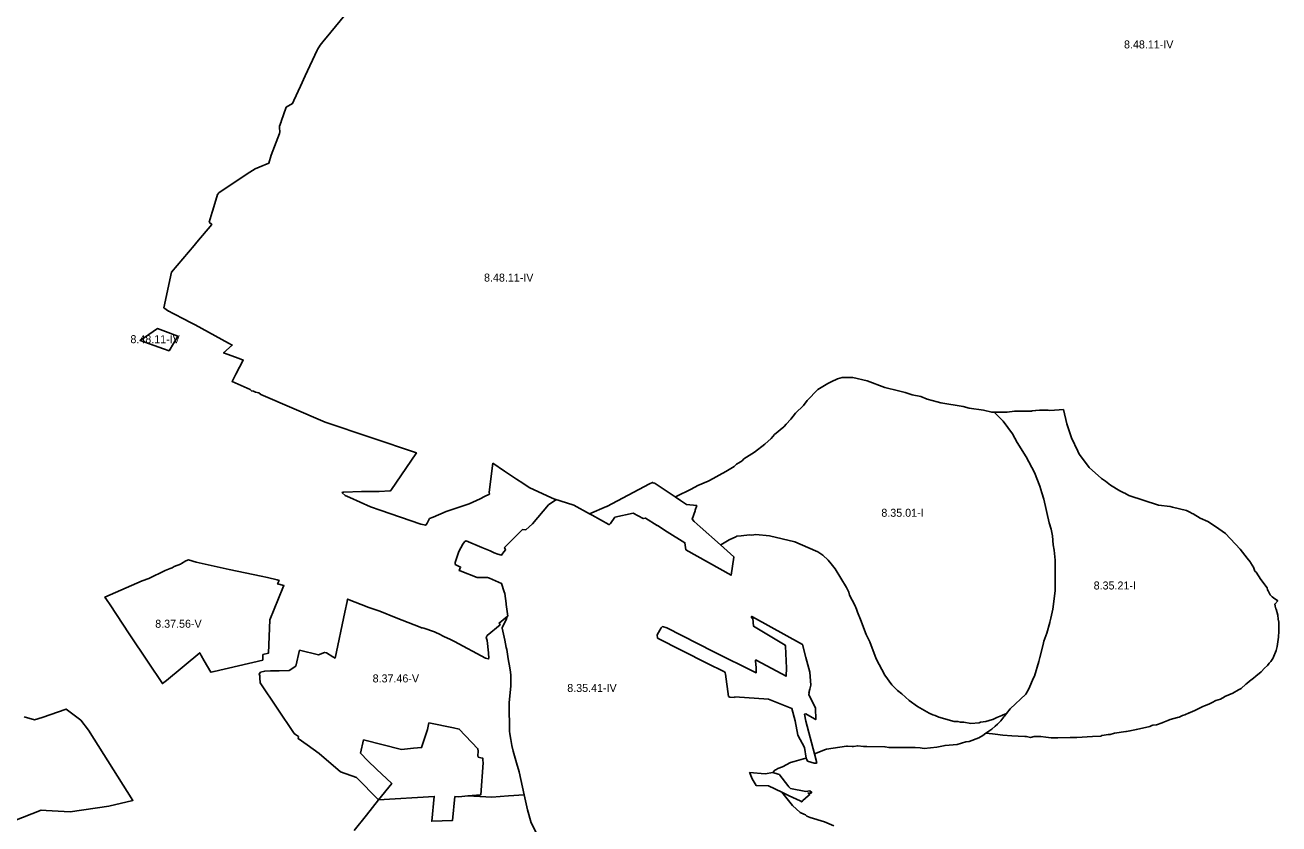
# Model space of a CAD drawing. Extents: x -444937 to -440470, y -1149084 to -1129741.
# Drawn here: x -443286 to -441720, y -1132039 to -1131040 of the extents above; entities that cross this region are included whole.
import ezdxf

# ---------------------------------------------------------------- set-up
doc = ezdxf.new("R2010")
doc.units = 0
doc.layers.add('Vrstva 28', color=7, linetype='Continuous')

msp = doc.modelspace()

# ---------------------------------------------------------------- linework, layer by layer
at = {"layer": 'Vrstva 28'}
for points in [[(-443113.15, -1131393.63), (-443103.68, -1131349.31), (-443075.35, -1131315.72), (-443071.83, -1131311.55), (-443053.26, -1131289.53), (-443056.45, -1131286.51), (-443055.2, -1131282.39), (-443052.68, -1131274.06), (-443052, -1131271.83), (-443046.06, -1131252.22), (-443044.11, -1131249.77), (-443005.5, -1131224.32), (-442999.16, -1131220.19), (-442993.96, -1131218), (-442981.76, -1131212.85), (-442978.94, -1131203.16), (-442968.4, -1131175.73), (-442968.32, -1131173.69), (-442968.47, -1131168.76), (-442968.46, -1131166.69), (-442966.56, -1131161.26), (-442966.43, -1131160.87), (-442960.2, -1131143.04), (-442952.18, -1131138.59), (-442950.71, -1131134.82), (-442942.42, -1131116.8), (-442942.39, -1131116.76), (-442936.4, -1131103.74), (-442921.53, -1131071.78), (-442921.33, -1131071.43), (-442921.05, -1131070.95), (-442917.86, -1131065.53), (-442914.32, -1131061.21), (-442904.54, -1131049.3), (-442887.1, -1131028.05)], [(-442626.15, -1131632.27), (-442628.86, -1131631.02), (-442656.65, -1131618.23), (-442664.68, -1131612.89), (-442672.47, -1131607.71), (-442687.37, -1131597.8), (-442702.14, -1131587.99), (-442706.86, -1131624.1), (-442706.45, -1131626.39), (-442712.53, -1131629.48), (-442718.17, -1131632.34), (-442731.84, -1131638.47), (-442760.3, -1131648.07), (-442776.82, -1131655.27), (-442781.2, -1131657.14), (-442784.1, -1131662.85), (-442786.01, -1131665.41), (-442791.96, -1131664.13), (-442842.68, -1131646.65), (-442854.89, -1131642.45), (-442880.78, -1131630.8), (-442886.56, -1131628.2), (-442886.64, -1131628.13), (-442890.17, -1131625.01), (-442889.75, -1131624.16), (-442888.05, -1131623.95), (-442866.36, -1131623.1), (-442844.26, -1131623.1), (-442830.44, -1131622.46), (-442829.38, -1131621.83), (-442797.54, -1131574.91), (-442911.64, -1131536.4), (-442991.79, -1131501.93), (-442994.55, -1131500.02), (-442998.59, -1131499.17), (-443001.14, -1131497.68), (-443003.69, -1131497.46), (-443005.4, -1131495.76), (-443027.88, -1131485.8), (-443023.15, -1131476.76), (-443013.87, -1131459.02), (-443019.04, -1131457.15), (-443038.38, -1131449.99), (-443027.63, -1131440.22), (-443032.18, -1131437.94), (-443073.85, -1131414.98), (-443083.04, -1131410.25), (-443085.34, -1131409.07), (-443103.18, -1131399.89), (-443105.88, -1131398.5), (-443106.11, -1131398.38), (-443107.1, -1131397.87), (-443113.15, -1131393.63)], [(-443095.75, -1131428.94), (-443106.54, -1131447.3), (-443113.62, -1131444.8), (-443131.18, -1131438.59), (-443142.76, -1131434.49), (-443120.91, -1131419.75), (-443114.47, -1131422.1)], [(-443114.47, -1131422.1), (-443095.75, -1131428.94)], [(-442474.49, -1131630), (-442473.06, -1131629.26), (-442454.42, -1131620.23), (-442446.28, -1131615.86), (-442433.1, -1131610.12), (-442431.6, -1131609.3), (-442411.2, -1131598.21), (-442400.79, -1131591.83), (-442398.02, -1131589.28), (-442397.75, -1131589.11), (-442394.94, -1131587.38), (-442390.8, -1131584.82), (-442388.46, -1131582.48), (-442375.49, -1131574.19), (-442362.52, -1131563.98), (-442354.65, -1131556.97), (-442350.19, -1131551.86), (-442338.71, -1131542.3), (-442338.35, -1131541.92), (-442335.59, -1131538.96), (-442329.78, -1131532.73), (-442324.04, -1131525.5), (-442314.26, -1131515.72), (-442309.37, -1131509.35), (-442296.19, -1131495.95), (-442283.65, -1131488.09), (-442279.64, -1131486.19), (-442271.53, -1131482.35), (-442265.79, -1131480.65), (-442252.4, -1131480.86), (-442234.54, -1131485.11), (-442212.43, -1131493.4), (-442195.64, -1131497.46), (-442186.92, -1131499.57), (-442178.41, -1131502.54), (-442167.36, -1131504.67), (-442159.7, -1131507.86), (-442147.32, -1131511.11), (-442142.7, -1131512.32), (-442114.63, -1131517), (-442106.98, -1131518.91), (-442089.12, -1131521.46)], [(-442089.12, -1131521.46), (-442078.92, -1131524.23), (-442075.85, -1131524.21)], [(-442075.85, -1131524.21), (-442059.78, -1131524.01), (-442050.43, -1131522.74), (-442043.63, -1131522.86), (-442040.93, -1131522.88), (-442029.17, -1131522.95), (-442028.32, -1131522.31), (-442024.21, -1131521.97), (-442023.77, -1131521.93), (-442019.51, -1131521.58), (-442018.12, -1131521.46), (-442014.6, -1131521.46), (-442008.76, -1131521.46), (-442006.21, -1131522.1), (-442000.63, -1131521.68), (-441994.94, -1131521.25), (-441989.36, -1131520.83)], [(-442075.85, -1131524.21), (-442064.89, -1131535.28), (-442052.98, -1131551.01), (-442047.03, -1131562.07), (-442035.97, -1131579.93), (-442025.56, -1131599.49), (-442018.96, -1131616.49), (-442016.35, -1131624.78), (-442013.86, -1131632.65), (-442007.27, -1131662.41), (-442004.93, -1131670.07), (-442003.23, -1131678.57), (-442002.38, -1131689.63), (-442000.89, -1131696.43), (-441999.62, -1131709.19), (-441999.63, -1131710.92), (-441999.66, -1131716), (-441999.74, -1131730.96), (-441999.83, -1131747.45), (-442002.81, -1131770.41), (-442003.58, -1131774.07), (-442005.09, -1131781.26), (-442006.21, -1131786.57), (-442006.24, -1131786.68), (-442010.04, -1131800.18), (-442013.86, -1131810.38), (-442014.79, -1131814.23), (-442018.75, -1131830.79), (-442020.28, -1131835.78), (-442025.77, -1131853.75), (-442026.8, -1131856.18), (-442032.57, -1131869.69), (-442036.4, -1131876.29), (-442055.96, -1131894.57), (-442060.5, -1131900.51)], [(-441989.36, -1131520.83), (-441985.29, -1131538.47), (-441984.95, -1131539.96), (-441979.21, -1131556.33), (-441971.4, -1131572.97), (-441971.27, -1131573.24), (-441969.43, -1131577.16), (-441957.1, -1131593.11), (-441942.01, -1131606.93), (-441936.69, -1131610.33), (-441930.53, -1131615.43), (-441919.05, -1131622.45), (-441913.87, -1131624.69), (-441912.67, -1131625.21), (-441907.57, -1131628.4), (-441870.57, -1131640.3), (-441856.12, -1131642.01), (-441853.35, -1131642.7), (-441835.71, -1131647.11), (-441831.53, -1131649.09), (-441828.53, -1131650.52), (-441827.2, -1131651.15), (-441818.7, -1131656.67), (-441808.92, -1131660.71), (-441799.35, -1131666.88), (-441787.02, -1131675.6), (-441768.53, -1131695.15), (-441759.88, -1131706.4), (-441756.29, -1131711.06), (-441755.77, -1131711.74), (-441751.73, -1131718.54), (-441751.53, -1131719.09), (-441750.24, -1131722.58), (-441748.76, -1131723.85), (-441743.02, -1131733), (-441735.15, -1131743.63), (-441734.51, -1131746.18), (-441733.83, -1131747.37), (-441731.11, -1131752.13), (-441730.35, -1131753.03), (-441728.77, -1131754.89), (-441727.25, -1131755.98), (-441721.67, -1131759.97), (-441725.58, -1131763.82), (-441724.93, -1131766.17), (-441724.91, -1131766.27), (-441723.93, -1131769.8), (-441723.8, -1131770.25), (-441721.76, -1131777.64), (-441721.06, -1131782.54), (-441721.03, -1131782.75), (-441720.48, -1131786.57), (-441720.27, -1131794.22), (-441720.43, -1131797.92), (-441720.47, -1131798.95), (-441720.69, -1131804), (-441720.83, -1131805.04), (-441722.4, -1131816.76), (-441723.67, -1131821.86), (-441727.29, -1131831.22), (-441727.89, -1131832), (-441730.52, -1131835.4), (-441732.27, -1131837.66), (-441734.51, -1131840.57), (-441738.08, -1131844.14), (-441742.59, -1131848.65), (-441749.17, -1131853.91), (-441752.07, -1131856.23), (-441756.87, -1131860.07), (-441760.48, -1131862.96), (-441761.73, -1131863.95), (-441767.25, -1131869.27), (-441770.63, -1131871.16), (-441777.88, -1131875.22), (-441787.88, -1131879.51), (-441788.3, -1131879.69), (-441793.4, -1131882.66), (-441798.93, -1131884.15), (-441799.06, -1131884.22), (-441803.7, -1131886.71), (-441806.94, -1131888.45), (-441807.65, -1131888.83), (-441813.17, -1131890.98), (-441815.3, -1131891.81), (-441825.98, -1131897.14), (-441827.2, -1131897.76), (-441831.79, -1131899.61), (-441832.49, -1131899.9), (-441837.79, -1131902.04), (-441840.55, -1131903.16), (-441843.13, -1131904.2), (-441845.06, -1131904.99), (-441846.93, -1131905.52), (-441856.12, -1131908.17), (-441859.09, -1131909.33), (-441865.43, -1131911.78), (-441866.19, -1131912.08), (-441873.13, -1131914.77), (-441877.56, -1131915.24)], [(-442581.26, -1131651.23), (-442560.23, -1131641.95), (-442559.94, -1131641.82), (-442506.26, -1131613.79), (-442502.6, -1131611.88), (-442501.78, -1131612.69), (-442500.61, -1131612.57), (-442474.49, -1131630)], [(-442626.15, -1131632.27), (-442623.5, -1131633.49), (-442632.52, -1131639.9), (-442652.51, -1131663.49), (-442660.94, -1131671.2), (-442665.15, -1131670.82), (-442687.5, -1131692.99), (-442686.39, -1131696.03), (-442689.51, -1131700.23), (-442691.48, -1131702.89), (-442695.82, -1131701.33), (-442700.55, -1131699.63), (-442705.62, -1131697.5), (-442716.08, -1131693.1), (-442735.41, -1131684.96), (-442737.11, -1131685.6), (-442737.62, -1131686.28), (-442739.66, -1131689), (-442744.55, -1131698.36), (-442749.02, -1131711.75), (-442749.23, -1131714.3), (-442746.04, -1131716.21), (-442742.38, -1131717.64), (-442744.01, -1131722.03), (-442742.8, -1131722.5), (-442721.57, -1131730.84), (-442708.78, -1131730.47), (-442706.21, -1131731.58), (-442691.21, -1131737.99), (-442687.78, -1131748.51), (-442687.16, -1131750.44), (-442685.54, -1131763), (-442685.35, -1131764.5), (-442683.49, -1131778.94), (-442684.04, -1131779.38)], [(-442581.26, -1131651.23), (-442600.88, -1131640.34), (-442626.15, -1131632.27)], [(-442474.49, -1131630), (-442467.65, -1131634.56), (-442460.25, -1131639.3), (-442447.44, -1131640.81), (-442449.28, -1131646.33), (-442449.59, -1131647.26), (-442453.09, -1131657.74), (-442450.53, -1131660.71), (-442443.02, -1131667.28), (-442417.69, -1131690.04)], [(-442417.69, -1131690.04), (-442401.23, -1131704.84), (-442401, -1131705.36), (-442404.55, -1131727.83), (-442461.25, -1131695.88), (-442462.31, -1131687.15), (-442484.25, -1131673.45), (-442496.67, -1131665.6), (-442496.9, -1131665.55), (-442511.57, -1131656.39), (-442514.35, -1131657.03), (-442526.66, -1131650.31), (-442549.62, -1131655.41), (-442555.14, -1131663.28), (-442556.42, -1131664.56), (-442557.27, -1131664.56), (-442578.14, -1131652.96), (-442581.26, -1131651.23)], [(-442060.5, -1131900.51), (-442064.74, -1131902.35), (-442066.32, -1131903.04), (-442072.42, -1131905.69), (-442077.64, -1131907.96), (-442077.93, -1131908.05), (-442086.15, -1131910.51), (-442092.95, -1131911.58), (-442094.65, -1131912.43), (-442105.28, -1131913.06), (-442114, -1131911.58), (-442118.03, -1131911.58), (-442121.22, -1131910.51), (-442126.11, -1131910.51), (-442145.25, -1131904.99), (-442149.75, -1131903.14), (-442152.4, -1131902.05), (-442157.15, -1131900.1), (-442171.61, -1131891.81), (-442182.03, -1131884.36), (-442191.17, -1131876.07), (-442196.69, -1131872.03), (-442201.14, -1131867.46), (-442203.71, -1131864.81), (-442203.92, -1131864.59), (-442212.64, -1131852.48), (-442223.27, -1131832.07), (-442231.35, -1131811.23), (-442234.98, -1131803.62), (-442235.81, -1131801.88), (-442243.06, -1131782.98), (-442246.59, -1131773.8), (-442248.04, -1131770.01), (-442249.84, -1131765.31), (-442256.65, -1131752.55), (-442257.5, -1131749.15), (-442260.26, -1131743.2), (-442274.5, -1131719.82), (-442279.63, -1131713.59), (-442283.43, -1131708.97), (-442290.02, -1131702.81), (-442296.4, -1131698.56), (-442308.67, -1131693.29), (-442325.1, -1131686.23), (-442356.57, -1131678.57), (-442373.57, -1131676.87), (-442378.66, -1131677.81), (-442381.23, -1131677.51), (-442388.57, -1131678.28), (-442391.77, -1131678.62), (-442397.39, -1131679.21), (-442398.74, -1131679.82), (-442406.74, -1131683.46), (-442417.25, -1131689.82), (-442417.69, -1131690.04)], [(-443109.56, -1131859.5), (-443114.86, -1131863.25), (-443132.66, -1131836.47), (-443156.25, -1131800.98), (-443180.25, -1131764.94), (-443184.82, -1131758.09), (-443186.77, -1131755.15), (-443140.17, -1131734.71), (-443131.67, -1131731.73), (-443111.26, -1131721.95), (-443105.22, -1131719.54), (-443102.76, -1131718.55), (-443100.21, -1131716.85), (-443092.33, -1131714.03), (-443091.19, -1131713.31), (-443085.75, -1131709.84), (-443082.35, -1131708.56), (-443072.57, -1131711.54), (-443050.04, -1131716.64), (-443031.62, -1131720.52), (-442991.7, -1131728.94), (-442983.5, -1131730.67), (-442971.59, -1131733.65), (-442969.1, -1131734.27), (-442970.99, -1131738.6), (-442963.15, -1131740.67), (-442964.32, -1131743.5), (-442980.83, -1131783.52)], [(-442844.92, -1132008.41), (-442872.59, -1131980.39), (-442892.43, -1131973.43), (-442919.05, -1131950.61), (-442934.22, -1131939.78), (-442945.11, -1131931.99), (-442944.76, -1131929.48), (-442948.42, -1131926.84), (-442950.12, -1131925.61), (-442992.79, -1131862.1), (-442992.88, -1131860.47), (-442993.03, -1131857.76), (-442993.28, -1131853.33), (-442993.91, -1131851.42), (-442992.22, -1131849.08), (-442987.11, -1131847.59), (-442979.92, -1131847.44), (-442968.95, -1131847.21), (-442956.5, -1131846.95), (-442948.23, -1131841.24), (-442943.42, -1131821.59), (-442919.82, -1131827.44), (-442912.28, -1131824.21), (-442909.73, -1131824.84), (-442902.08, -1131829.73), (-442899.27, -1131831.31), (-442886.99, -1131773.82), (-442884.19, -1131760.74), (-442883.54, -1131757.68), (-442857.12, -1131767.97), (-442855.74, -1131768.51), (-442843.41, -1131772.76), (-442822.8, -1131780.88), (-442793.08, -1131792.6), (-442791.11, -1131793.38), (-442790.73, -1131793.44), (-442789.88, -1131793.56), (-442788.13, -1131793.81), (-442774.95, -1131798.7), (-442772.47, -1131799.89), (-442769.43, -1131800.96), (-442763.2, -1131804.32), (-442754.88, -1131808.31), (-442750.08, -1131810.6)], [(-442980.83, -1131783.52), (-442982.22, -1131825.01), (-442989.29, -1131826.95), (-442989.47, -1131833.79), (-443050.23, -1131848.05), (-443054.17, -1131848.98), (-443062.53, -1131834.67), (-443066.41, -1131828.03), (-443068.32, -1131824.76), (-443109.56, -1131859.5)], [(-442750.08, -1131810.6), (-442711.18, -1131831.43), (-442707.78, -1131832.28), (-442706.93, -1131831.65), (-442707.35, -1131824.84), (-442709.27, -1131809.54), (-442710.33, -1131805.71), (-442709.05, -1131803.16), (-442693.06, -1131789.64), (-442694.27, -1131787.69), (-442684.04, -1131779.38)], [(-442684.04, -1131779.38), (-442685.69, -1131783.42), (-442690.56, -1131792.96), (-442690.33, -1131794.04), (-442687.26, -1131808.78), (-442685.35, -1131817.96), (-442684.8, -1131820.6), (-442684.18, -1131823.57), (-442682.81, -1131832.44), (-442681.07, -1131843.69), (-442680.24, -1131849.08), (-442679.72, -1131852.48), (-442679.5, -1131866.08), (-442681.84, -1131887.13), (-442681.8, -1131889.46), (-442681.2, -1131922.21), (-442681.13, -1131922.76), (-442680.72, -1131925.78), (-442679.72, -1131933.26), (-442678.72, -1131938.1), (-442678.25, -1131940.38), (-442676.74, -1131947.72), (-442671.7, -1131965.11), (-442670.01, -1131970.7), (-442669.36, -1131973.63), (-442663.04, -1132002.17)], [(-442310.84, -1131956.44), (-442312.98, -1131943.04), (-442321.28, -1131927.73), (-442324.68, -1131909.88), (-442328.5, -1131894.36), (-442357.84, -1131882.66), (-442399.72, -1131879.9), (-442400.36, -1131880.54), (-442405.58, -1131880.35), (-442406.31, -1131880.32), (-442407.59, -1131879.26), (-442411.6, -1131851.56), (-442411.84, -1131849.92), (-442412.91, -1131848.65), (-442434.9, -1131837.6), (-442496.62, -1131806.26), (-442496.85, -1131802.1), (-442495.39, -1131799.33), (-442491.78, -1131793.37), (-442490.08, -1131791.88), (-442484.97, -1131793.37), (-442426.94, -1131823.1), (-442373.03, -1131849.75), (-442373.36, -1131843.55), (-442374.21, -1131834.62), (-442373.5, -1131833.55), (-442372.24, -1131834.23), (-442335.86, -1131854.01), (-442335.89, -1131853.45), (-442335.73, -1131853.54), (-442335.52, -1131843.97), (-442336.77, -1131816.53), (-442336.83, -1131815.08), (-442376.48, -1131791.58), (-442377.45, -1131781.82), (-442378.89, -1131780.97), (-442378.89, -1131779.34), (-442378.8, -1131779.23), (-442377.65, -1131779.86), (-442315.4, -1131814.29), (-442311.08, -1131830.58), (-442306.18, -1131849.07)], [(-442306.18, -1131849.07), (-442304.91, -1131865.23), (-442306.14, -1131870.17), (-442307.25, -1131874.58), (-442307.16, -1131874.94), (-442307.61, -1131876.76), (-442298.99, -1131893.75), (-442298.88, -1131908.08), (-442300.23, -1131907.32), (-442311.28, -1131901.16), (-442312.77, -1131901.37), (-442312.74, -1131901.56), (-442311.28, -1131910.3), (-442300.38, -1131950.76)], [(-443287.71, -1131904.56), (-443274.76, -1131908.41), (-443265.1, -1131905.44), (-443235.17, -1131894.99), (-443216.91, -1131908.94), (-443207.08, -1131921.42), (-443151.63, -1132009.21), (-443181.71, -1132016.16), (-443230.23, -1132023.48), (-443259.97, -1132021.67), (-443266.19, -1132021.29), (-443301.34, -1132034.98)], [(-442086.47, -1131925.14), (-442078.92, -1131920.29), (-442074.6, -1131916.42), (-442071.64, -1131913.77), (-442068.71, -1131911.15), (-442067.7, -1131909.84), (-442063.92, -1131904.94), (-442063.16, -1131903.95), (-442060.5, -1131900.51)], [(-442844.92, -1132008.41), (-442828.36, -1131988.15), (-442847.35, -1131970.18), (-442858.29, -1131959.62), (-442867.41, -1131950.05), (-442863.64, -1131933.68), (-442816.22, -1131945.4), (-442801.17, -1131944.02), (-442791.19, -1131943.1), (-442783.65, -1131920.6), (-442781.94, -1131912.37), (-442751.11, -1131918.53), (-442744.11, -1131919.96), (-442720.75, -1131944.53), (-442720.4, -1131947.49), (-442720.32, -1131948.14), (-442720.96, -1131953.24), (-442720.32, -1131954.94), (-442717.01, -1131955.85), (-442714.45, -1131956.55), (-442714.58, -1131958.85)], [(-441877.56, -1131915.24), (-441879.08, -1131915.4), (-441881.63, -1131916.68), (-441898.32, -1131920.56), (-441906.29, -1131922.42), (-441910.76, -1131923.05), (-441911.3, -1131923.13), (-441925.85, -1131925.18), (-441930.95, -1131926.67), (-441933.57, -1131927), (-441941.16, -1131927.95), (-441941.57, -1131928.15), (-441942.86, -1131928.8), (-441943.26, -1131928.82), (-441953.28, -1131929.47), (-441972.62, -1131930.71), (-441980.9, -1131930.76), (-441996.31, -1131930.87), (-442004.93, -1131930.92), (-442011.57, -1131930.04), (-442017.69, -1131929.22), (-442026.19, -1131929.43), (-442030.45, -1131930.5), (-442035.55, -1131929.43), (-442037.59, -1131929.3), (-442046.15, -1131928.75), (-442053.71, -1131928.27), (-442065.31, -1131927.52), (-442074.74, -1131926.46), (-442077.93, -1131926.1), (-442086.47, -1131925.14)], [(-442300.38, -1131950.76), (-442286.6, -1131945.56), (-442285.56, -1131945.17), (-442260.37, -1131941.54), (-442258.99, -1131941.34), (-442253.22, -1131941.67), (-442251.54, -1131941.77), (-442246.44, -1131940.91), (-442239.21, -1131941.98), (-442235.05, -1131942.01), (-442212.43, -1131942.19), (-442207.17, -1131943.07), (-442206.05, -1131943.25), (-442200.8, -1131943.22), (-442174.59, -1131943.04), (-442168.37, -1131943.64), (-442163.53, -1131944.1), (-442147.37, -1131942.61), (-442137.17, -1131940.49), (-442122.29, -1131939.21), (-442111.23, -1131936.02), (-442106.98, -1131935.6), (-442095.07, -1131931.14), (-442089.97, -1131928.16), (-442086.47, -1131925.14)], [(-442714.58, -1131958.85), (-442714.31, -1131962.14), (-442717.05, -1132002.08), (-442733.41, -1132003.52)], [(-442352.38, -1131974.45), (-442349.34, -1131970.89), (-442348.78, -1131971.08), (-442348.7, -1131971.1), (-442346.36, -1131969.4), (-442340.41, -1131967.06), (-442330.2, -1131961.75), (-442325.84, -1131960.55), (-442311.38, -1131956.59), (-442310.84, -1131956.44)], [(-442300.38, -1131950.76), (-442297.46, -1131962.39), (-442298.39, -1131962.44), (-442300.87, -1131962.6), (-442308.95, -1131960.05), (-442310.84, -1131956.44)], [(-442357.99, -1131990.77), (-442373.15, -1131990.66), (-442378.04, -1131982.16), (-442380.59, -1131975.99), (-442381.45, -1131974.36), (-442362.09, -1131975.78), (-442352.38, -1131974.45)], [(-442352.38, -1131974.45), (-442345.58, -1131976.45), (-442344.24, -1131976.84), (-442343.64, -1131977.63), (-442333.8, -1131990.45), (-442332.33, -1131992.36), (-442331.6, -1131993.02), (-442330.2, -1131994.28), (-442311.17, -1131997.89), (-442306.12, -1131997.3), (-442303.89, -1131999.22), (-442304.64, -1132000), (-442308.42, -1132000), (-442306.25, -1132001.67), (-442308.07, -1132003.56), (-442314.9, -1132009.27), (-442316.28, -1132010.94), (-442316.39, -1132011.08), (-442318.23, -1132009.71), (-442332, -1132003.35), (-442341.18, -1131998.91)], [(-442341.18, -1131998.91), (-442357.99, -1131990.77)], [(-442875.47, -1132046.72), (-442860.07, -1132027.41), (-442844.92, -1132008.41)], [(-442733.41, -1132003.52), (-442744.45, -1132004.49), (-442749.45, -1132004.44), (-442752.41, -1132034.14), (-442778.39, -1132035.21), (-442775.35, -1132004.21), (-442844.92, -1132008.41)], [(-442663.04, -1132002.17), (-442682.71, -1132003.64), (-442703.22, -1132004.96), (-442733.41, -1132003.52)], [(-442663.04, -1132002.17), (-442658.9, -1132020.83), (-442654.27, -1132037.04), (-442647.66, -1132050.27), (-442633.17, -1132061.48)], [(-442276.39, -1132040.9), (-442287.7, -1132036.05), (-442305.76, -1132030.53), (-442310.01, -1132028.82), (-442311.56, -1132027.28), (-442311.71, -1132027.12), (-442313.62, -1132026.49), (-442318.09, -1132024.15), (-442328, -1132015.49), (-442341.18, -1131998.91)]]:
    msp.add_lwpolyline(points, dxfattribs=at)

# ---------------------------------------------------------------- texts
for s, p in [('8.48.11-IV', (-441913.75, -1131069.62)), ('8.48.11-IV', (-442713.14, -1131360.92)), ('8.48.11-IV', (-443154.81, -1131437.88)), ('8.35.01-I', (-442216.85, -1131654.78)), ('8.35.21-I', (-441951.67, -1131745.63)), ('8.37.56-V', (-443123.82, -1131793.45)), ('8.37.46-V', (-442852.28, -1131861.75)), ('8.35.41-IV', (-442609.17, -1131873.67))]:
    msp.add_text(s, height=10, dxfattribs=at).set_placement(p)

doc.saveas('drawing.dxf')
